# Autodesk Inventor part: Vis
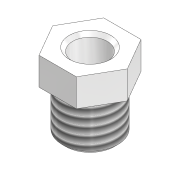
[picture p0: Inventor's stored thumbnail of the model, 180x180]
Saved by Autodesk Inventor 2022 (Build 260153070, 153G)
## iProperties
Created: 2018-06
Part Number: Vis
Material: Laiton, jaune doux
Document SubType Name: Modeling
Designer: Fabian Perrée
Density: 8.47 g/cm^3
Appearance: Neige
Author: Fabian Perrée
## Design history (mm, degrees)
sketch "Esquisse1"
  geometry: C1 r 6 at (0, 0); C2 r 3.75 at (0, 0); 1 further point
  constraints: 2 centre point, 2 coincident
  dimensions: "d0" = 12 diameter of C1; "d1" = 7.5 diameter of C2
extrude "Extrusion1" new body sketch "Esquisse1" distance "d2" = 16; taper "d3" = 0 deg
sketch "Esquisse2"
  geometry: L1 (4.041, -7)-(-4.041, -7); L2 (-4.041, -7)-(-8.083, 0); L3 (-8.083, 0)-(-4.041, 7); L4 (-4.041, 7)-(4.041, 7); L5 (4.041, 7)-(8.083, 0); L6 (8.083, 0)-(4.041, -7); C1 r 3.75 at (0, 0) reference; C2 r 6 at (0, 0) reference; 1 further point
  constraints: 12 end point, 1 coincident, 1 horizontal, 13 other
  dimensions: "d4" = 14 distance between parallel lines of L4 L1
extrude "Extrusion2" join sketch "Esquisse2" distance "d5" = 6; taper "d6" = 0 deg
chamfer "Chanfrein1" distance "d7" = 0.75; stored, may be unused: second distance "d8" = 2, angle "d9" = 45 deg
feature "Filetage1" dims "d10" = 10, "d11" = 0
node "Solide1"
